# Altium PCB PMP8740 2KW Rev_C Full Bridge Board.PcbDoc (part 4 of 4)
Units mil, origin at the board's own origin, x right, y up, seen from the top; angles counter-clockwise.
Board outline 10366.14 x 5900 mil, 2 copper layers (Top Layer, Bottom Layer), stack 62 mil thick; 355 components, 213 nets, 1059 pads, 574 vias.
Unrouted connection lines stored in the file: 2.
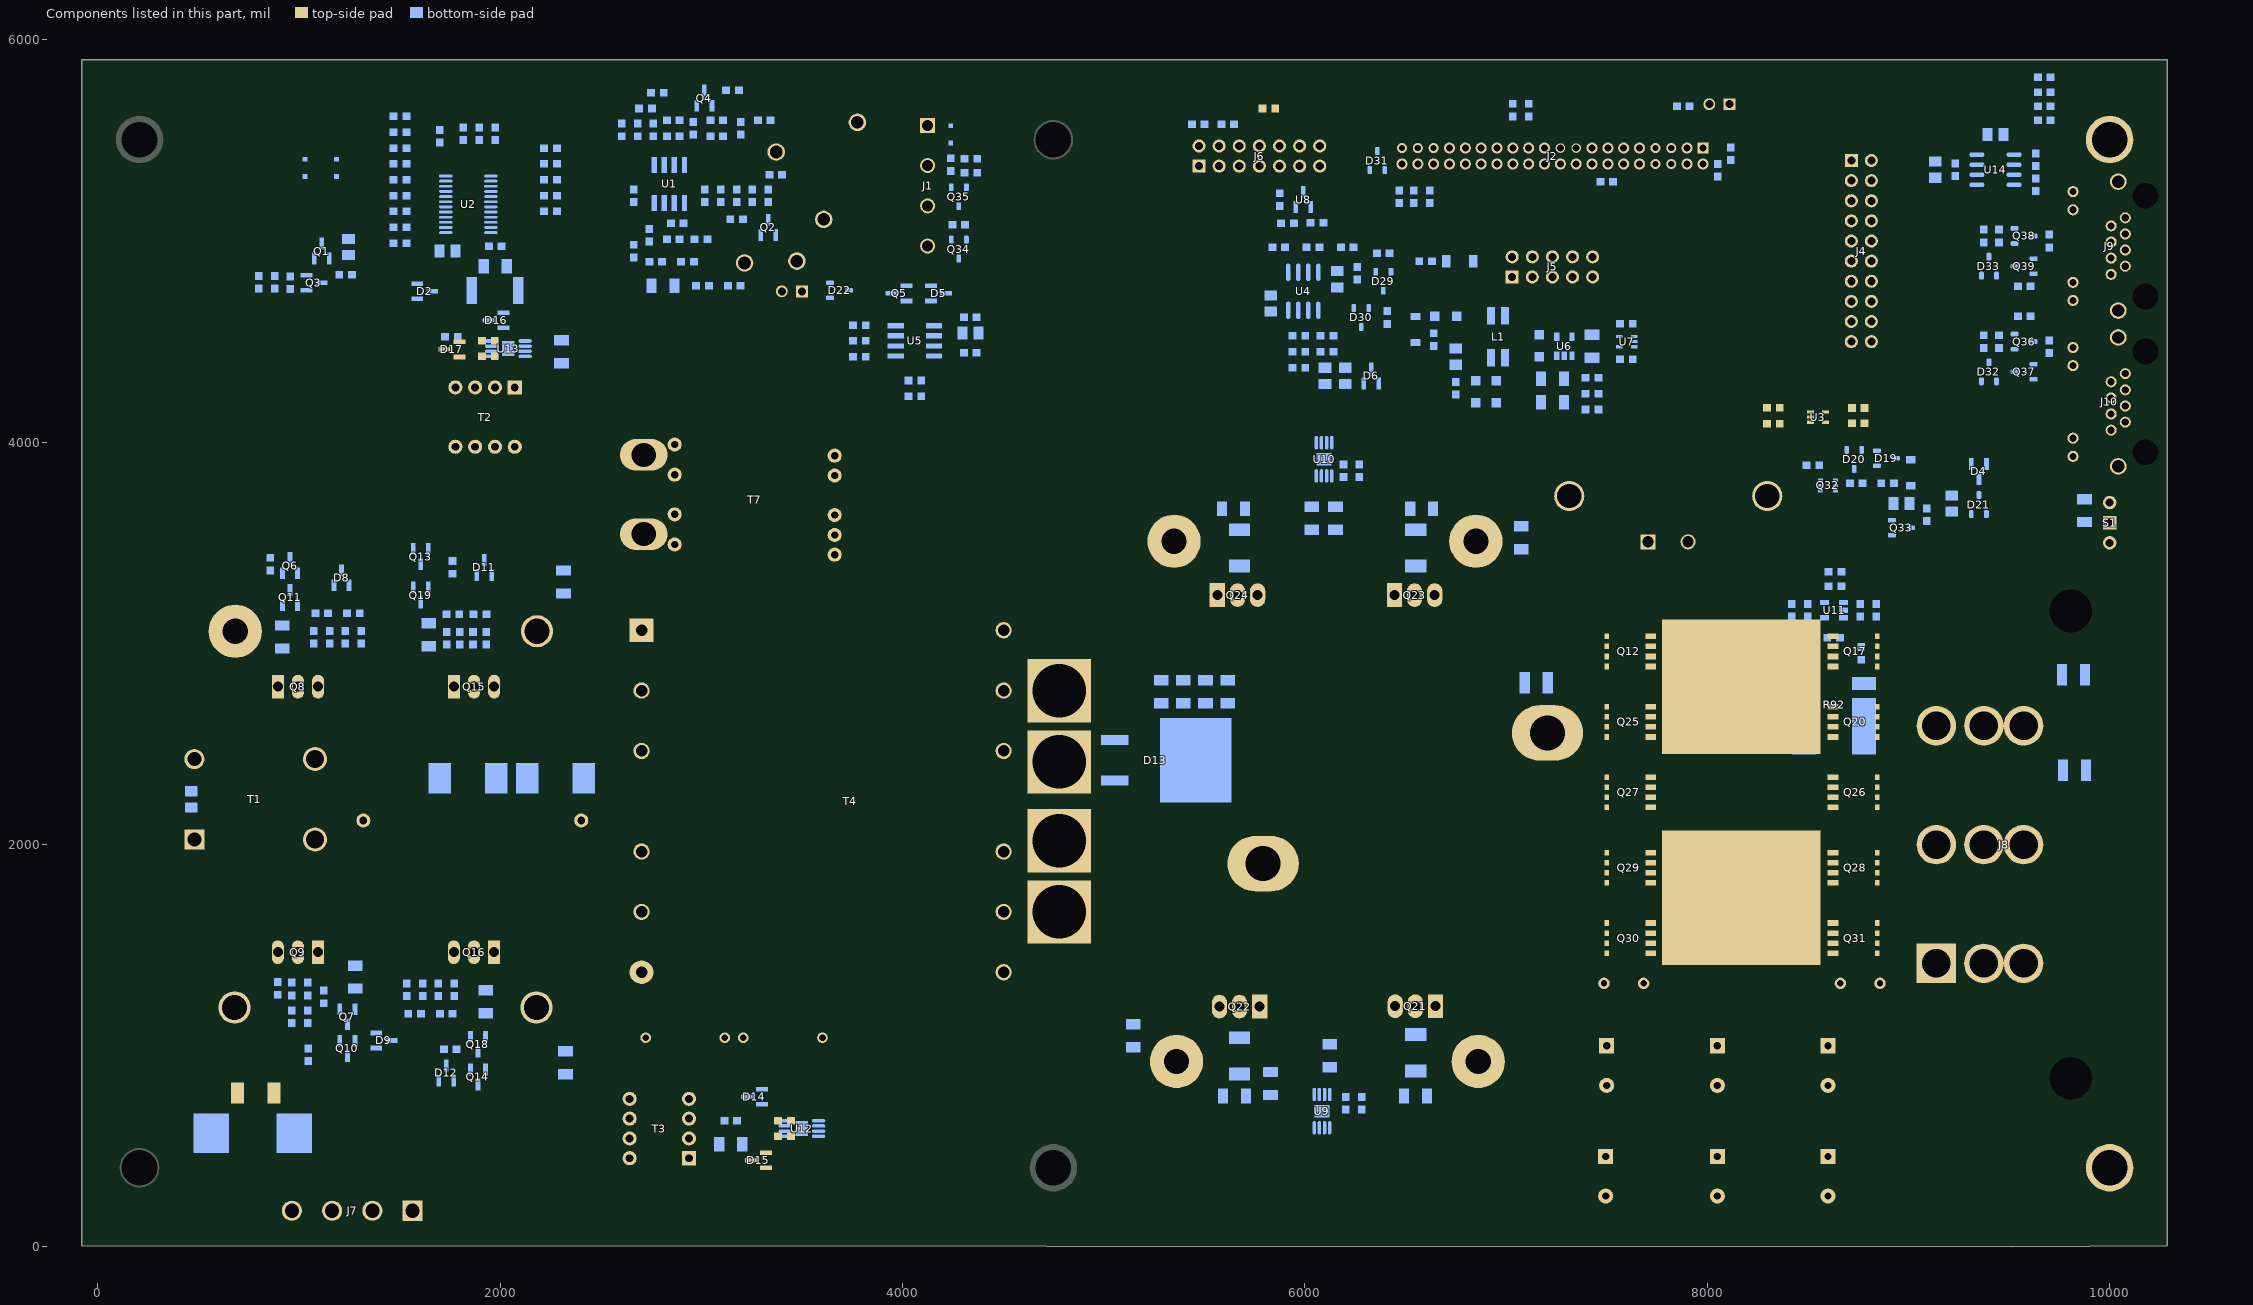
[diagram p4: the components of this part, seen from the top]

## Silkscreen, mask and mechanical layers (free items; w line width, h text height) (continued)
M12 Stackup:
  lines w6: 11360,7460 13910,7460 ; 11360,7564.4 13910,7564.4 ; 11300,6975 ccw(c11334,6975) 11334,6941 13936,6941 ccw(c13936,6975) 13970,6975 13970,7681 ccw(c13936,7681) 13936,7715 11334,7715 ccw(c11334,7681) 11300,7681 11300,6975
  text "The Stackup Legend below this is static." at 11605.5,7874.5 h60
  text "If you change the stackup, update the Legend." at 11615.5,7784.5 h60
  text "Layer Stack Up Detail for: Ref_Design.PcbDoc" at 11360,7597.1 h57
  text "Layer" at 11360,7525.4 h24
  text "Gerber" at 12255.81,7525.4 h24
  text "Copper" at 12819.33,7525.4 h24
  text "Dielectric" at 13422.04,7525.4 h24
  text "Name" at 11360,7477.4 h24
  text "Document" at 12255.81,7477.4 h24
  text "Thickness" at 12819.33,7477.4 h24
  text "Material" at 13422.04,7477.4 h24
  text "Top Solder Mask" at 11360,7384.44 h34
  text "(.GTS)" at 12255.81,7384.44 h34
  text "Solder Resist" at 13422.04,7384.44 h34
  text "Top Layer" at 11360,7287.69 h34
  text "(.GTL)" at 12255.81,7287.69 h34
  text "1.4mil" at 12819.33,7287.69 h34
  text "FR-4" at 13422.04,7239.31 h34
  text "Bottom Layer" at 11360,7190.94 h34
  text "(.GBL)" at 12255.81,7190.94 h34
  text "1.4mil" at 12819.33,7190.94 h34
  text "Bottom Solder Mask" at 11360,7094.19 h34
  text "(.GBS)" at 12255.81,7094.19 h34
  text "Solder Resist" at 13422.04,7094.19 h34
  text ".Layer_Name" at 577,-858.49 h60
M13 Component Bodies Top:
  text ".Layer_Name" at 577,-858.49 h60
M14 Component Bodies Bottom:
  text ".Layer_Name" at 577,-858.49 h60
M15 Courtyards Top:
  text ".Layer_Name" at 577,-858.49 h60
M16 Courtyards Bottom:
  text ".Layer_Name" at 577,-858.49 h60
Drill Drawing:
  text ".Layer_Name" at 577,-858.49 h60

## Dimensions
-78.74,5 to 10287.4,5 on M2 Board Dimensions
